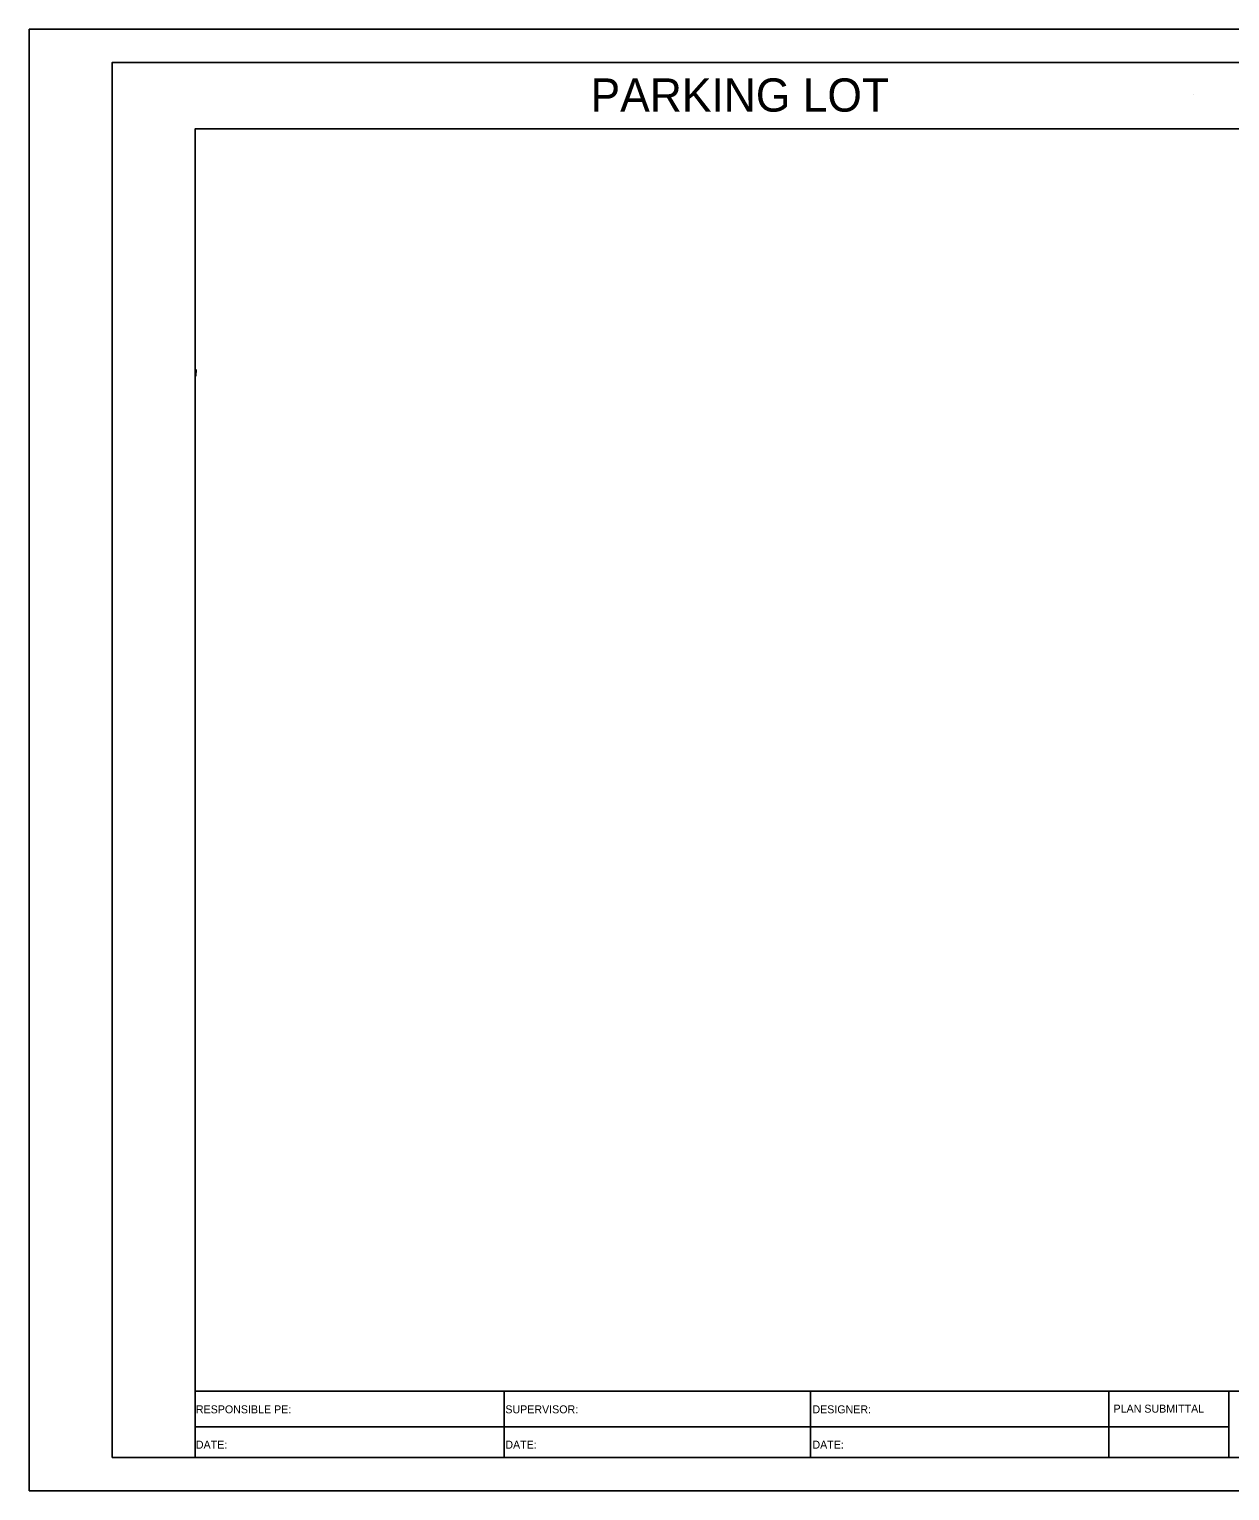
# Model space of a CAD drawing. Extents: x 1797478 to 1802796, y 246529 to 250952.
# Drawn here: x 1802116 to 1802296.8, y 250064.4 to 250284.4 of the extents above; entities that cross this region are included whole.
import ezdxf

# ---------------------------------------------------------------- set-up
doc = ezdxf.new("R2010")
doc.units = 0
for name, color, linetype in [('2', 7, 'Continuous'), ('ANNO-SHT', 7, 'Continuous'), ('ANNO-TXT', 7, 'Continuous'), ('AXIS', 7, 'Continuous'), ('DRAINAGE', 7, 'Continuous'), ('Level 1', 7, 'Continuous'), ('Level 62', 7, 'Continuous'), ('SHT-BDR', 7, 'Continuous'), ('SHT-BNDRY', 7, 'Continuous')]:
    doc.layers.add(name, color=color, linetype=linetype)

# ---------------------------------------------------------------- blocks, each defined once
blk = doc.blocks.new('SC47208')
at = {"layer": 'Level 1'}
blk.add_line((0, 0), (0, 0), dxfattribs=at)

msp = doc.modelspace()

# ---------------------------------------------------------------- linework, layer by layer
at = {"layer": '2'}
msp.add_lwpolyline([(1802141.12, 250233.21), (1802141.1, 250232.21)], dxfattribs=at)
msp.add_lwpolyline([(1802141.12, 250233.21), (1802141.1, 250232.21)], dxfattribs=at)
at = {"layer": 'AXIS'}
msp.add_line((1802141, 250189.42), (1802141, 250189.43), dxfattribs=at)
at = {"layer": 'Level 62'}
msp.add_lwpolyline([(1802116, 250064.42), (1802456, 250064.42), (1802456, 250284.42), (1802116, 250284.42)], close=True, dxfattribs=at)
at = {"layer": 'SHT-BDR'}
msp.add_lwpolyline([(1802141, 250079.43), (1802441, 250079.43), (1802441, 250269.43), (1802141, 250269.43)], close=True, dxfattribs=at)
at = {"layer": 'SHT-BNDRY'}
for p, q in [((1802141, 250069.42), (1802141, 250079.43)), ((1802187.52, 250079.43), (1802187.52, 250069.42)), ((1802233.67, 250069.42), (1802233.67, 250079.43)), ((1802278.59, 250069.42), (1802278.59, 250079.43)), ((1802296.63, 250069.42), (1802296.63, 250079.43)), ((1802141, 250074.03), (1802296.63, 250074.03))]:
    msp.add_line(p, q, dxfattribs=at)
msp.add_lwpolyline([(1802128.5, 250069.42), (1802451, 250069.42), (1802451, 250279.42), (1802128.5, 250279.42)], close=True, dxfattribs=at)

# ---------------------------------------------------------------- block references
at = {"layer": 'DRAINAGE', "xscale": 0.2, "yscale": 0.20000000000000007, "rotation": -116.41666666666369}
msp.add_blockref('SC47208', (1802291.32, 250274.62), dxfattribs=at)
msp.add_blockref('SC47208', (1802291.32, 250274.62), dxfattribs=at)

# ---------------------------------------------------------------- texts
at = {"layer": 'ANNO-SHT'}
msp.add_text('                    PARKING LOT             ', height=4.9995, rotation=360, dxfattribs=at).set_placement((1802163.38, 250272.02))
at = {"layer": 'ANNO-TXT'}
for s, p in [('RESPONSIBLE PE:', (1802141.1, 250076.08)), ('SUPERVISOR:', (1802187.7, 250076.08)), ('DESIGNER:', (1802233.94, 250076.08)), ('PLAN SUBMITTAL', (1802279.28, 250076.18)), ('DATE:', (1802141.1, 250070.76)), ('DATE:', (1802187.7, 250070.76)), ('DATE:', (1802233.94, 250070.76))]:
    msp.add_text(s, height=1.2, rotation=360, dxfattribs=at).set_placement(p)

doc.saveas('drawing.dxf')
